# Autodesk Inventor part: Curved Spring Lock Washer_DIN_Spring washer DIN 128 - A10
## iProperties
Shininess: 64.0
Length Units: 11269
Angle Units: 11279
Time Units: 11290
Mass Units: 11283
Length Display Precision: 3
Angle Display Precision: 2
Compacted: True
Part Number: Curved Spring Lock Washer_DIN_Spring washer DIN 128 - A10
Document SubType Name: Modeling
Created: 2006-11
Material: Par défaut
Designer: profs_sti
Density: 0.0
Volumn: 0.0
Area: 0.0
PropertySet Name: Model Information
Control State: 0
Master: False
Checked Out: False
Author: profs_sti
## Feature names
1. Base1
